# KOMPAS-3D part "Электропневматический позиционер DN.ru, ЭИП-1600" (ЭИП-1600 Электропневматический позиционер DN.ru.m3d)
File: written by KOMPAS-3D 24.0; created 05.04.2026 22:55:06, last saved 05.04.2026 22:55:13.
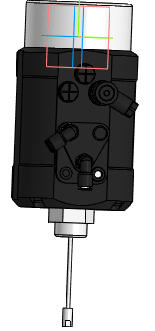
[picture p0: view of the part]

Document properties: Автор: R2D2; Полное имя файла: C:\Users\R2D2\Desktop\ЭИП-1600 Электропневматический позиционер DN.ru — копия\25-50\ЭИП-1600 Электропневматический позиционер DN.ru.m3d

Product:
- Part/product: Электропневматический позиционер DN.ru  | designation ЭИП-1600
    Масса: 0.14
    Раздел спецификации: Прочие изделия
    Примечание: D900-02860

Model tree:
1. Операция без истории:1

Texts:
  ЭИП-1600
